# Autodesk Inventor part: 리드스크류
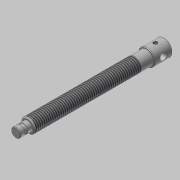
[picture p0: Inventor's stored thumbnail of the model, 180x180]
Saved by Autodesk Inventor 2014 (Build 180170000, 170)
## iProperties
Created: 2019-04
Part Number: 리드스크류
Material: 강철, 연강
Document SubType Name: Modeling
Designer: mduedu
Density: 1 g/cm^3
Appearance: 강철
Author: mduedu
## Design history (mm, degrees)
sketch "스케치1"
  geometry: C1 r 6 at (0, 0); 1 further point
  constraints: 1 centre point, 1 coincident
  dimensions: "d0" = 12 diameter of C1
extrude "돌출1" new body sketch "스케치1" distance "d1" = 100; taper "d2" = 0 deg
sketch "스케치2"
  geometry: C1 r 4 at (0, 0); 1 further point
  constraints: 1 centre point, 1 coincident
  dimensions: "d3" = 8 diameter of C1
extrude "돌출2" join sketch "스케치2" distance "d4" = 10; taper "d5" = 0 deg
sketch "스케치3"
  geometry: C1 r 7 at (0, 0); 1 further point
  constraints: 1 centre point, 1 coincident
  dimensions: "d9" = 14 diameter of C1
extrude "돌출3" join sketch "스케치3" distance "d10" = 15; taper "d11" = 0 deg
feature "스레드1" dims "d12" = 90, "d13" = 0
chamfer "모따기2" distance "d14" = 1; stored, may be unused: second distance "d15" = 2, angle "d16" = 45 deg
chamfer "모따기3" distance "d17" = 0.5; stored, may be unused: second distance "d18" = 2, angle "d19" = 45 deg
chamfer "모따기4" distance "d20" = 0.5; stored, may be unused: second distance "d21" = 2, angle "d22" = 45 deg
sketch "스케치4"
  geometry: L1 (-100, -5)-(-100, 5) reference; L2 (-109.5, 4)-(-109.5, -4) reference; L3 (-109.5, 0)-(-100, 0); C1 r 1.25 at (-105, 4); 1 further point
  constraints: 2 end point, 2 midpoint, 1 centre point
  dimensions: "d23" = 2.5 diameter of C1; "d24" = 5 distance from line of C1.centre L1; "d25" = 4 distance from line of C1.centre L3
revolve "회전1" sketch "스케치4" stored, may be unused: angle "d26" = 90 deg
sketch "스케치5"
  geometry: L1 (0, -6.5)-(0, 6.5) reference; C1 r 3 at (7.5, 0); 2 further points
  constraints: 1 centre point, 1 horizontal alignment, 1 midpoint
  dimensions: "d27" = 6 diameter of C1; "d28" = 7.5 distance from line of C1.centre L1
extrude "돌출4" cut sketch "스케치5" stored distance "d29" = 15; taper "d30" = 0 deg
node "작업 평면1"
sketch "스케치6"
  geometry: L1 (0, 6.5)-(0, -6.5) reference; 2 further points
  constraints: 1 horizontal alignment
  dimensions: "d31" = 7.5 distance from line of point (-7.5, 0) L1
hole "구멍1" sketch "스케치6" at (-7.5, 0) diameter "d32" = 3.242; stored, may be unused: countersink angle "d36" = 90 deg, drill point angle "d38" = 118 deg; dims "d33" = 6, "d34" = 4, "d35" = 2, "d37" = 8
node "솔리드1"
